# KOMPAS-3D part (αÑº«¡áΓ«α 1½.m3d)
File: created 29.01.2016 13:47:21, last saved 26.07.2016 19:34:20.
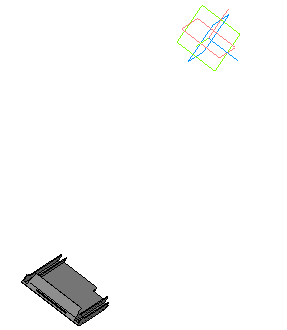
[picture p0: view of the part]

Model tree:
1. Эскиз:1
2. Операция выдавливания:1
     Толщина стенки 1 = 2; Толщина стенки 2 = 8; Расстояние 1 = 1
3. Эскиз:2
4. Операция выдавливания:2
     Толщина стенки 1 = 2; Толщина стенки 2 = 8; Расстояние 1 = 5
5. Эскиз:3
6. Операция выдавливания:3
     Толщина стенки 1 = 2; Толщина стенки 2 = 8; Расстояние 1 = 1
7. Эскиз:4
8. Операция выдавливания:4
     Толщина стенки 1 = 2; Толщина стенки 2 = 2.5; Расстояние 1 = 50
9. Эскиз:5
10. Вырезать элемент выдавливания:1
     Толщина стенки 2 = 1.2; Расстояние 1 = 40
11. Эскиз:6
12. Операция выдавливания:5
     Толщина стенки 1 = 2; Толщина стенки 2 = 2.5; Расстояние 1 = 10
13. Эскиз:7
14. Операция выдавливания:6
     Толщина стенки 1 = 2; Толщина стенки 2 = 8; Расстояние 1 = 1
15. Эскиз:8
16. Операция выдавливания:7
     Толщина стенки 1 = 2; Толщина стенки 2 = 8; Расстояние 1 = 5
17. Эскиз:9
18. Операция выдавливания:8
     Толщина стенки 1 = 2; Толщина стенки 2 = 8; Расстояние 1 = 1
19. Эскиз:10
20. Вырезать элемент выдавливания:2
     Толщина стенки 2 = 1.2; Расстояние 1 = 23
21. Эскиз:11
22. Вырезать элемент выдавливания:3
     Толщина стенки 2 = 1.2; Расстояние 1 = 1
23. Эскиз:12
24. Вырезать элемент выдавливания:4
     Расстояние 1 = 100
25. Эскиз:13
26. Операция выдавливания:9
     Расстояние 1 = 10; Расстояние 2 = 0.4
